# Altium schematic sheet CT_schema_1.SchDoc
size 620 x 511 mm
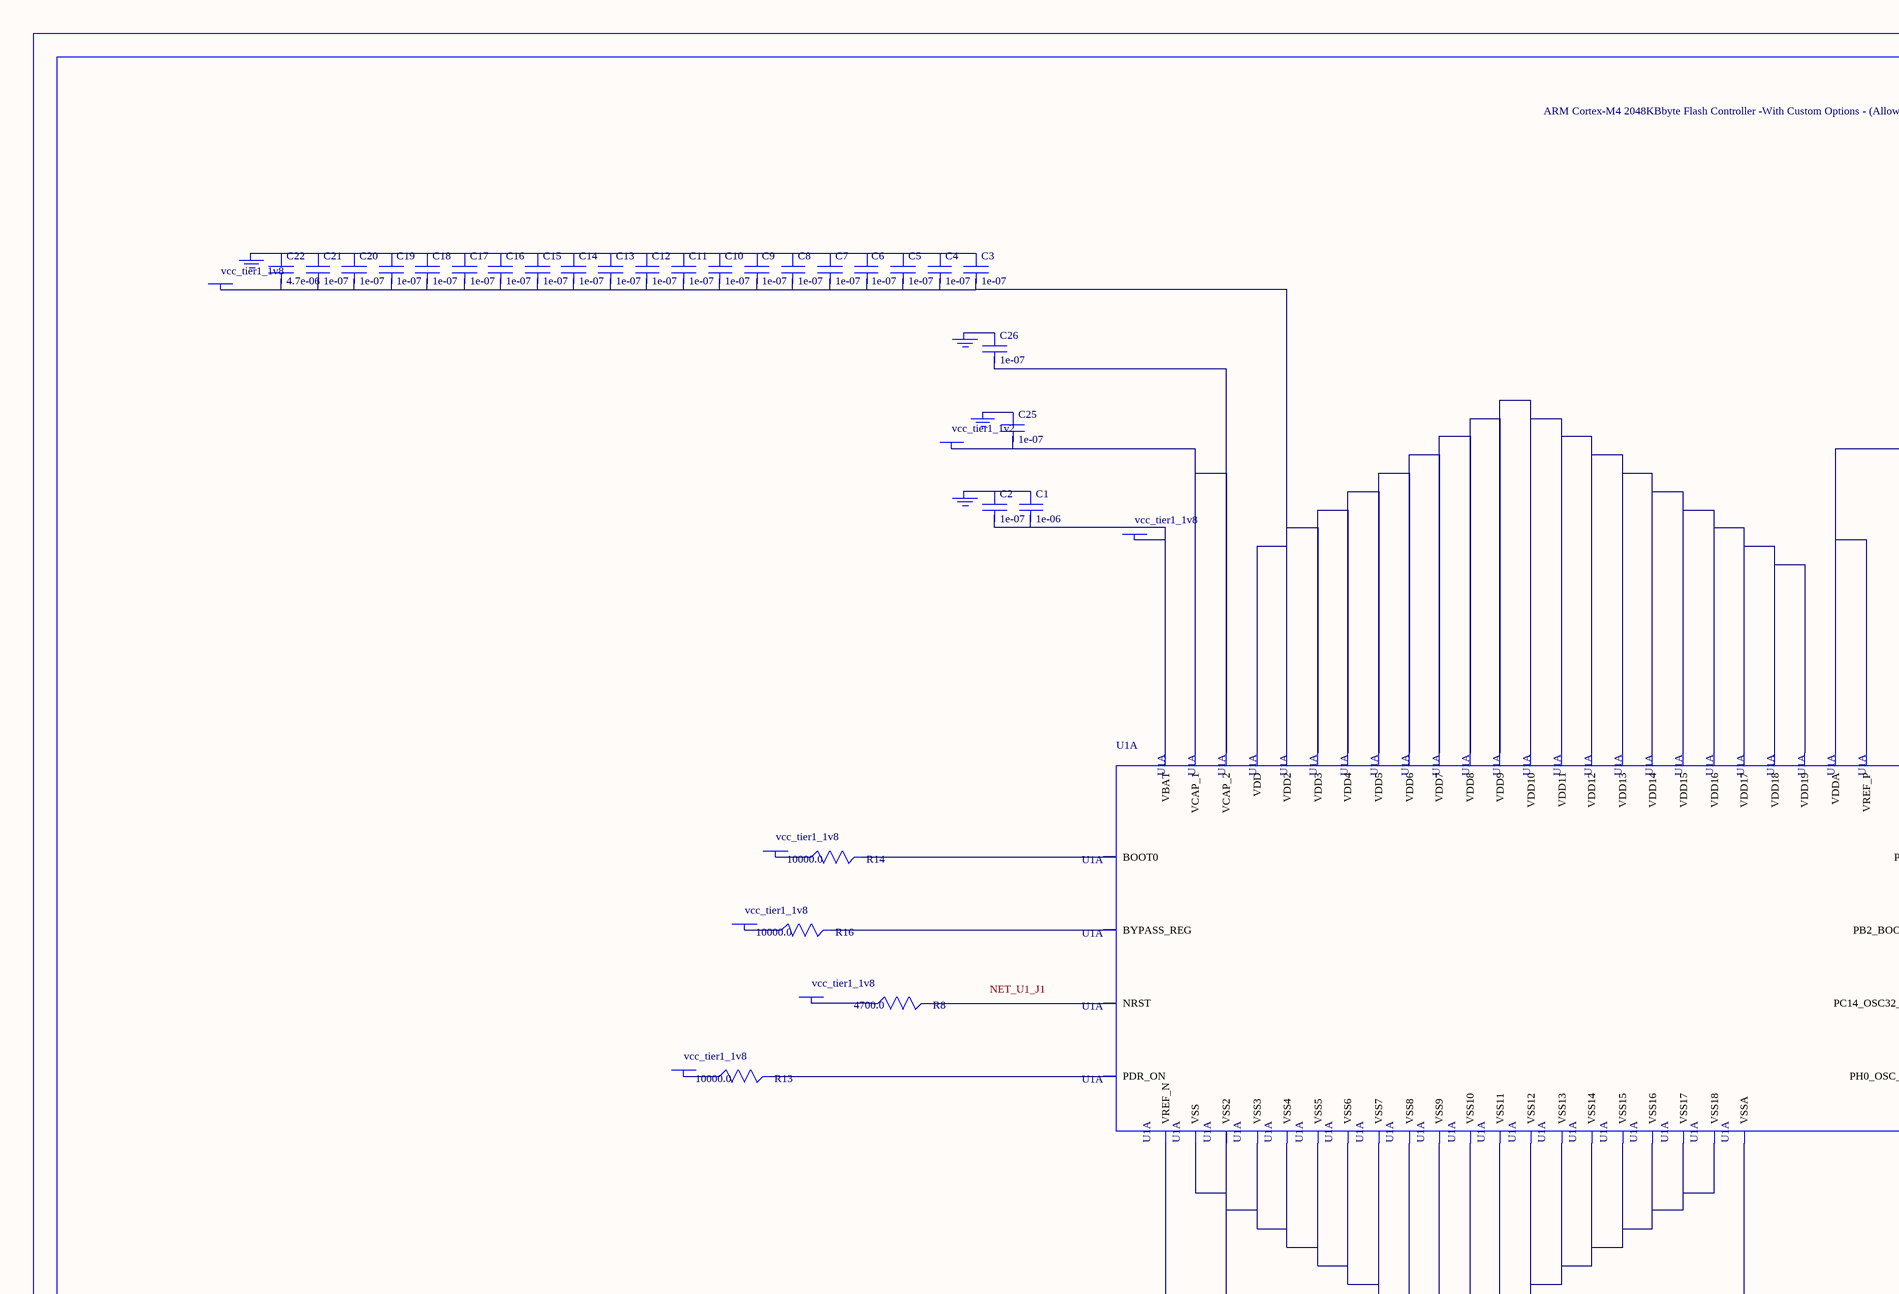
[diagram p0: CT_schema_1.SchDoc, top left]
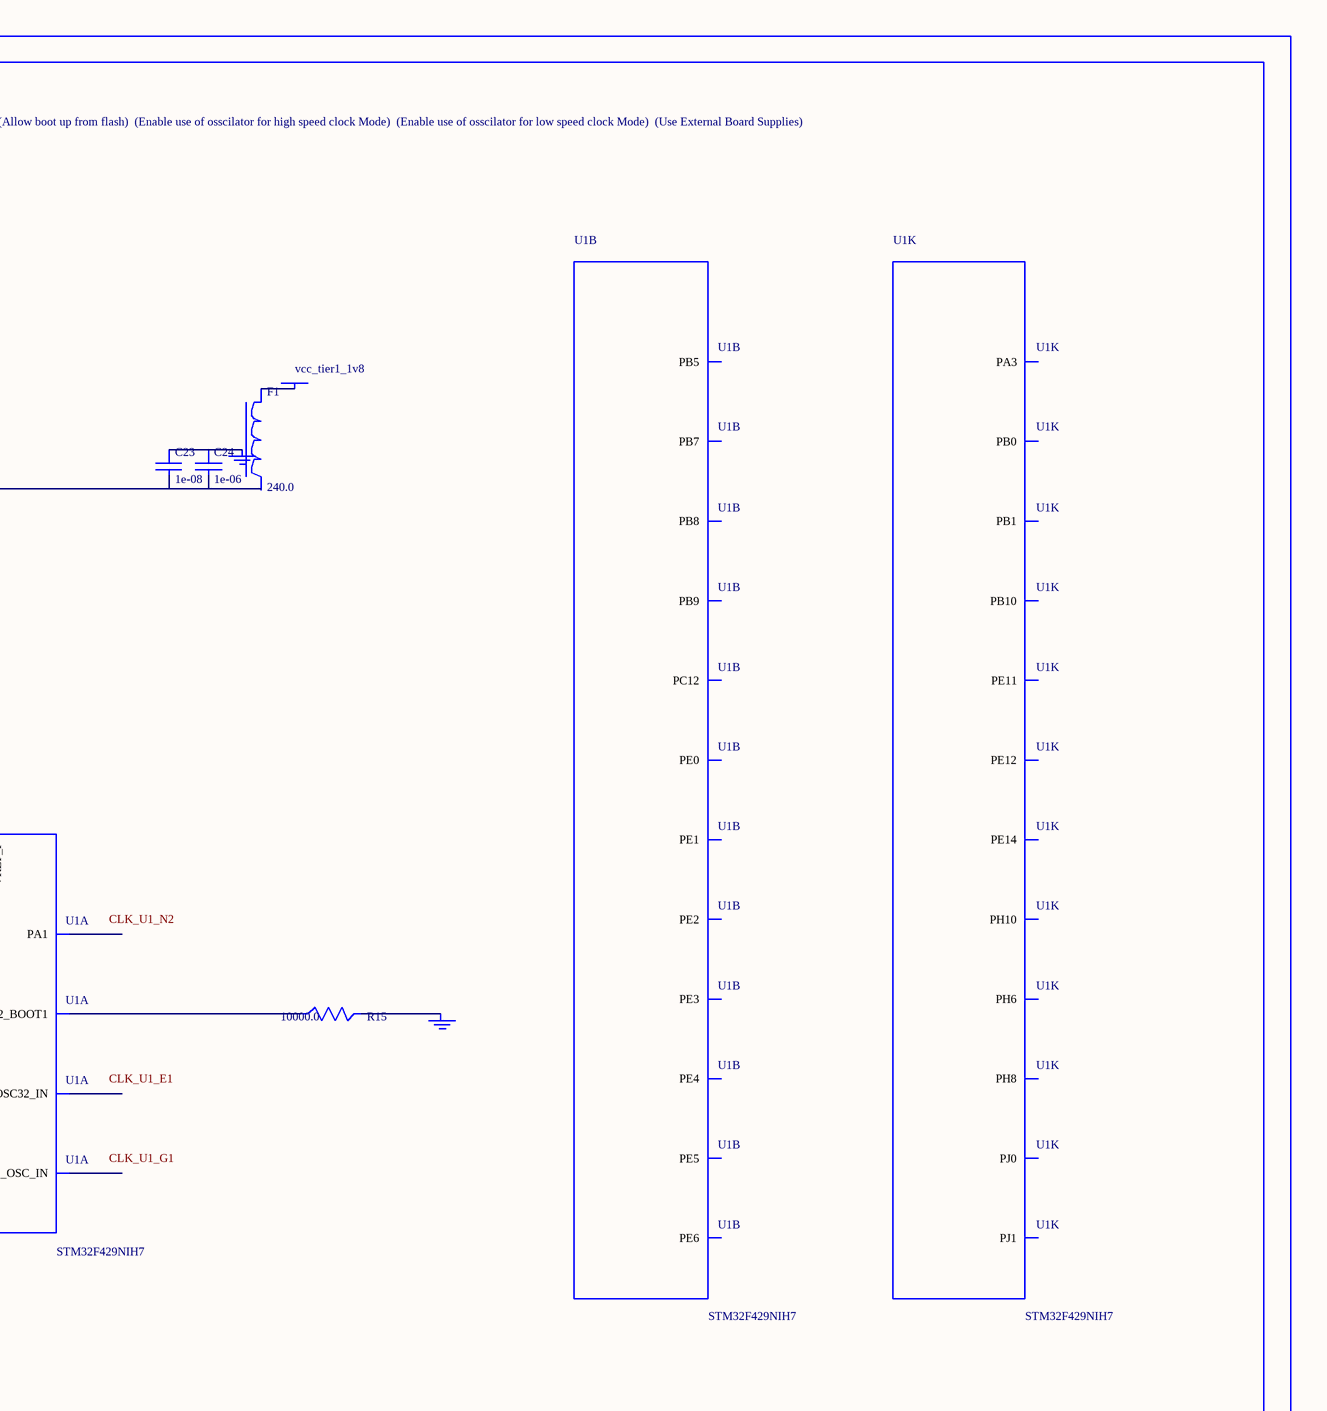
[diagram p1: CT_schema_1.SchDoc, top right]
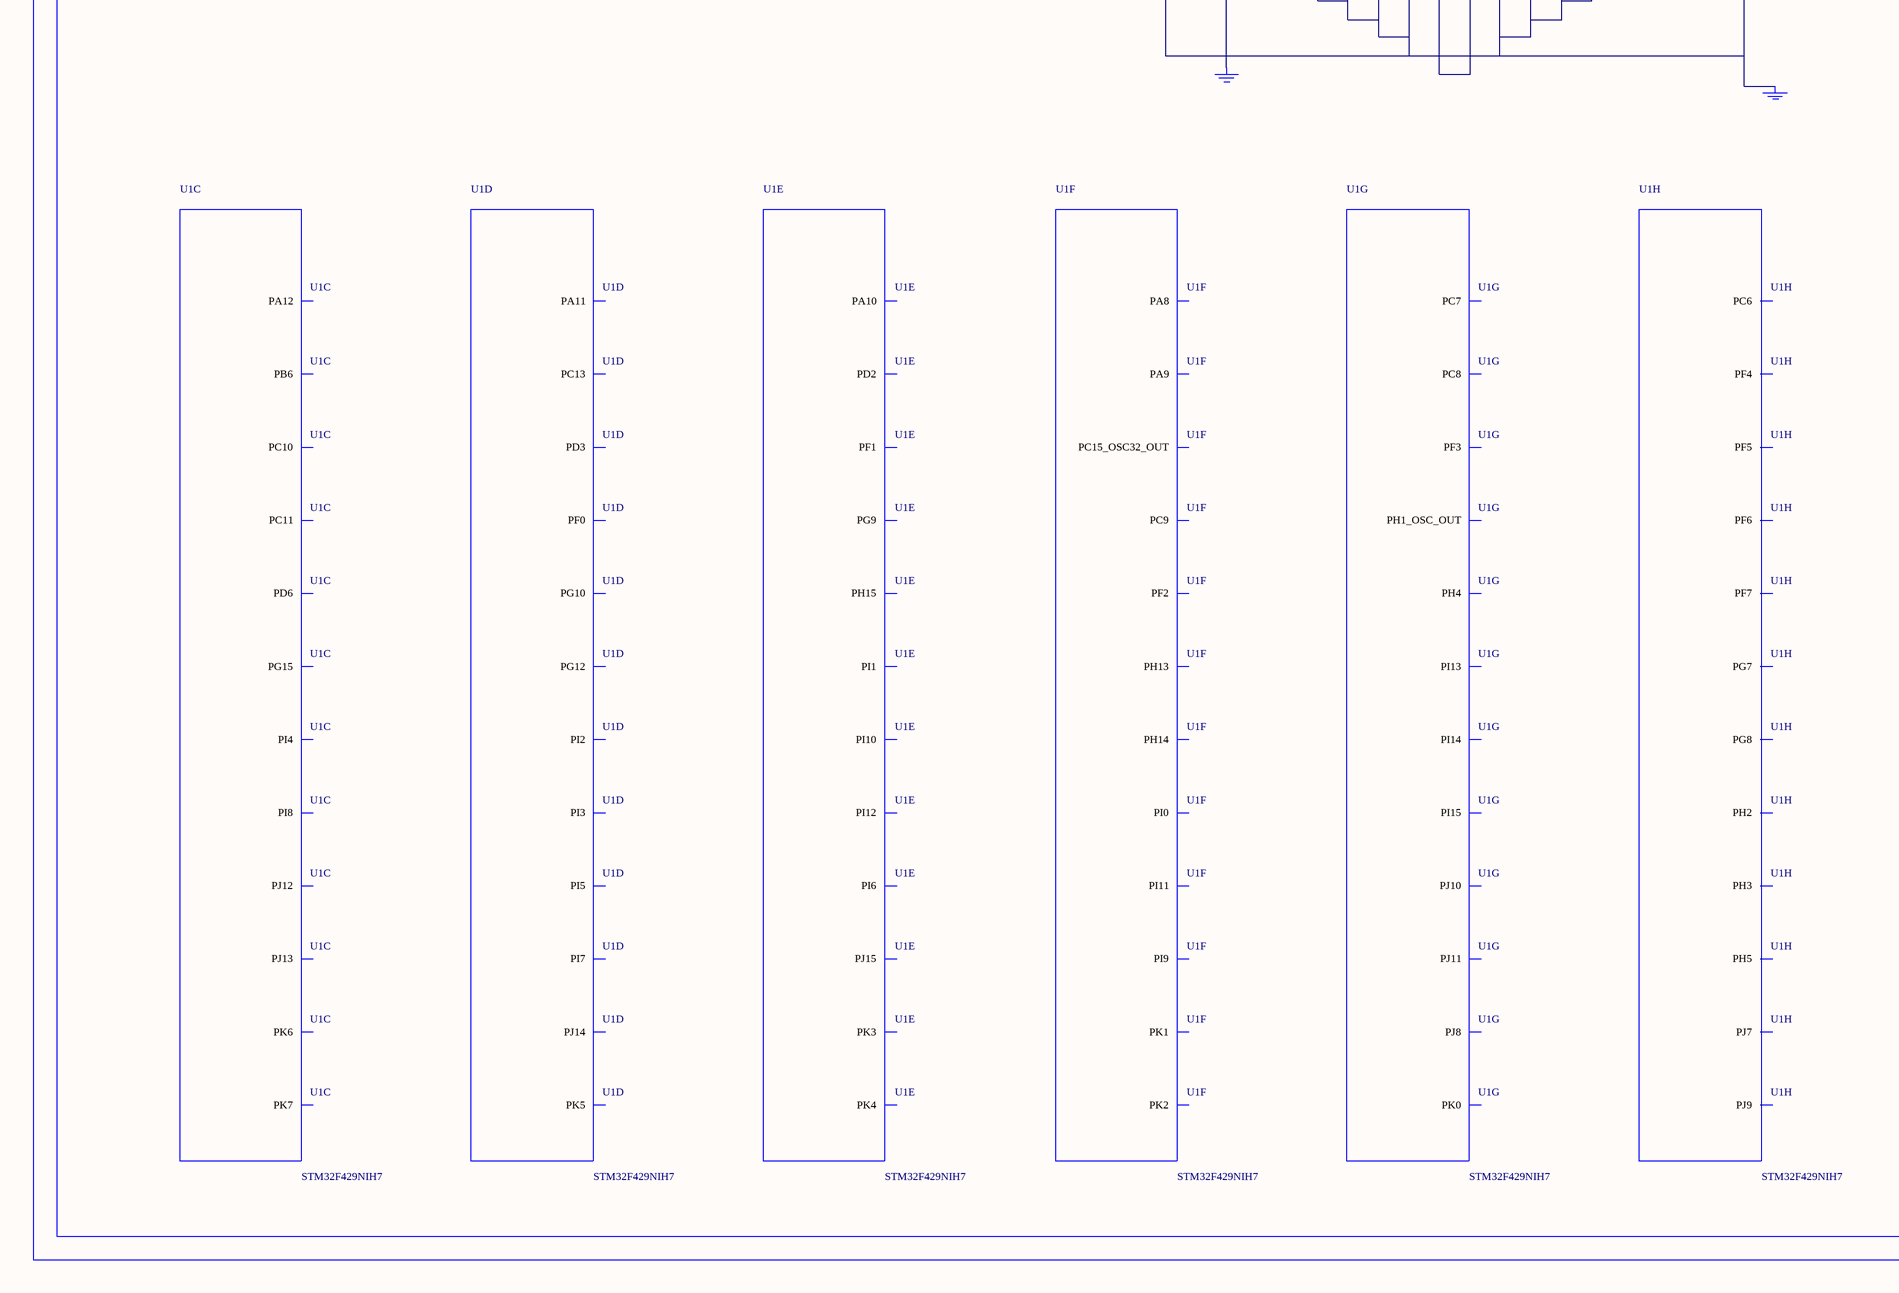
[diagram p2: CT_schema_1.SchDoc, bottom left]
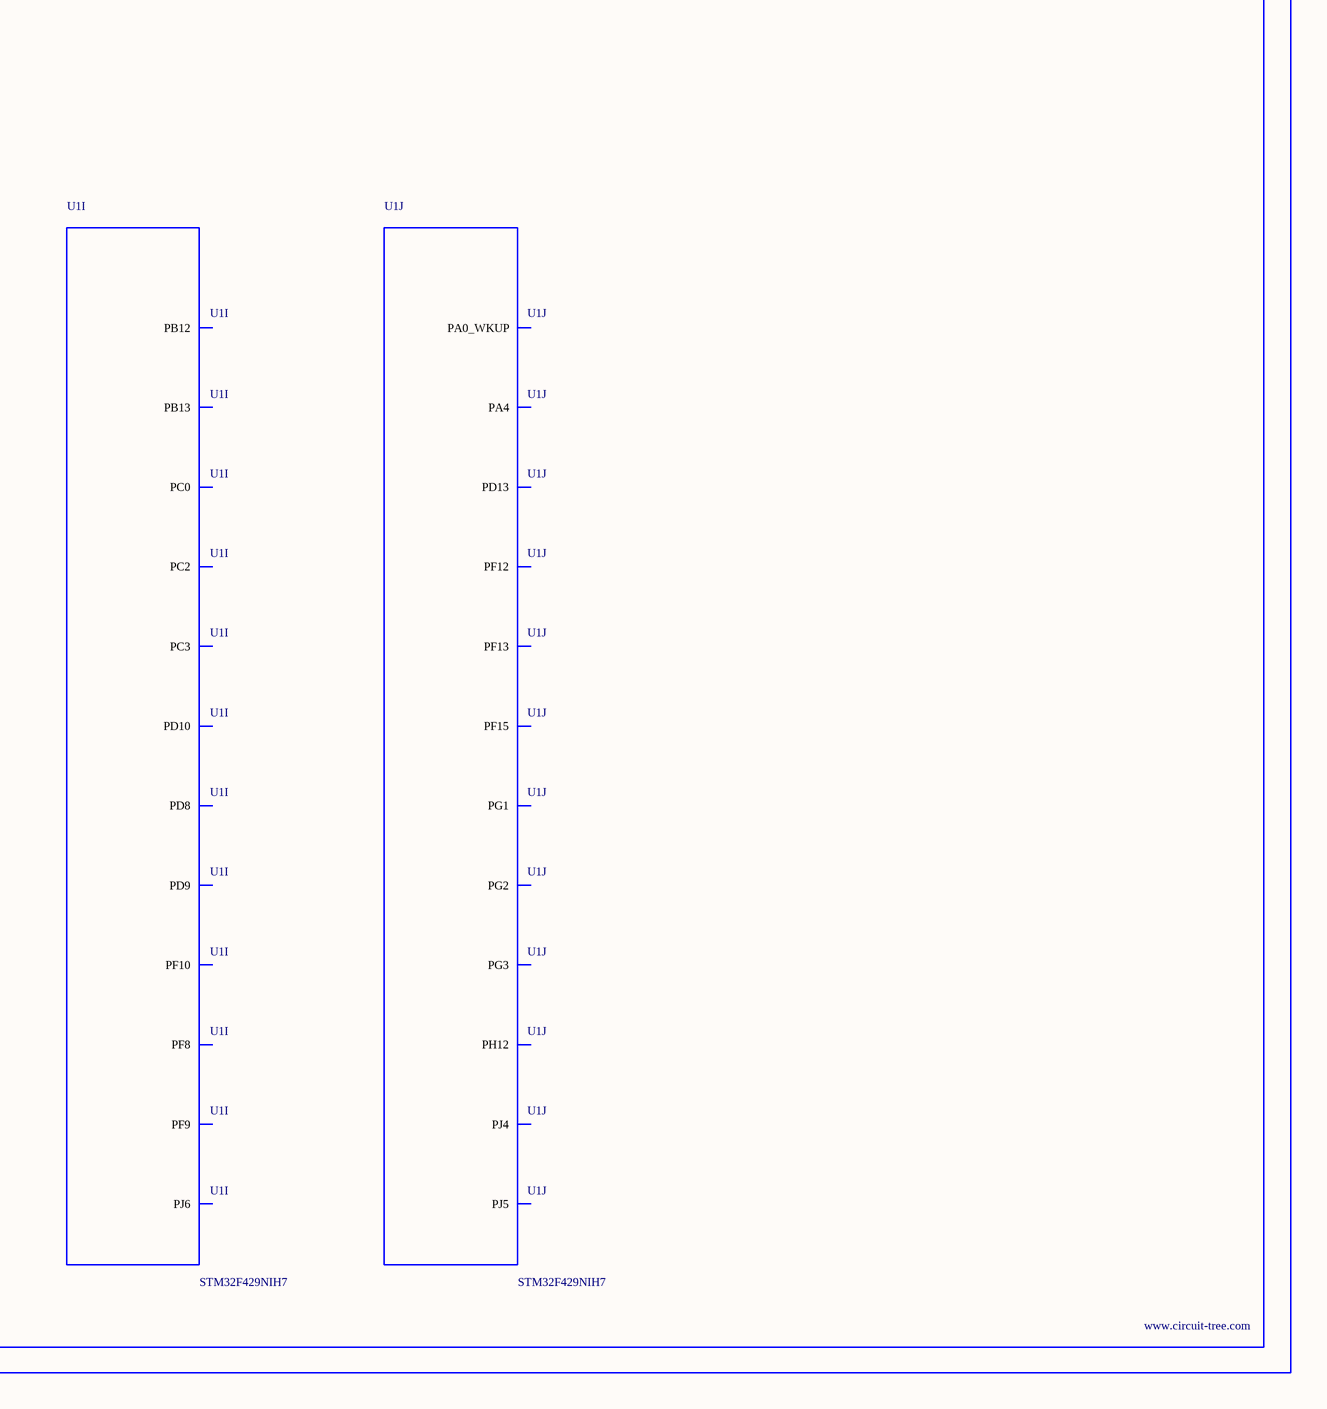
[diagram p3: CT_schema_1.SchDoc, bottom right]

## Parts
BORDER0  (no value)
C1  1e-06  [C0603]
C2  1e-07  [C0603]
C3  1e-07  [C0603]
C4  1e-07  [C0603]
C5  1e-07  [C0603]
C6  1e-07  [C0603]
C7  1e-07  [C0603]
C8  1e-07  [C0603]
C9  1e-07  [C0603]
C10  1e-07  [C0603]
C11  1e-07  [C0603]
C12  1e-07  [C0603]
C13  1e-07  [C0603]
C14  1e-07  [C0603]
C15  1e-07  [C0603]
C16  1e-07  [C0603]
C17  1e-07  [C0603]
C18  1e-07  [C0603]
C19  1e-07  [C0603]
C20  1e-07  [C0603]
C21  1e-07  [C0603]
C22  4.7e-06  [C0603]
C23  1e-08  [C0603]
C24  1e-06  [C0603]
C25  1e-07  [C0402]
C26  1e-07  [C0402]
F1  240.0  [L0603]
GND_INSTANCE_0_0  (no value)
GND_INSTANCE_0_1  (no value)
GND_INSTANCE_0_2  (no value)
GND_INSTANCE_0_3  (no value)
GND_INSTANCE_0_4  (no value)
GND_INSTANCE_0_5  (no value)
GND_INSTANCE_0_6  (no value)
GND_INSTANCE_0_7  (no value)
POWER_INSTANCE_0_0  vcc_tier1_1v8
POWER_INSTANCE_0_1  vcc_tier1_1v8
POWER_INSTANCE_0_2  vcc_tier1_1v8
POWER_INSTANCE_0_3  vcc_tier1_1v8
POWER_INSTANCE_0_4  vcc_tier1_1v8
POWER_INSTANCE_0_5  vcc_tier1_1v8
POWER_INSTANCE_0_6  vcc_tier1_1v2
POWER_INSTANCE_0_7  vcc_tier1_1v8
R8  4700.0  [R0603]
R13  10000.0  [R0603]
R14  10000.0  [R0603]
R15  10000.0  [R0603]
R16  10000.0  [R0603]
U1  STM32F429NIH7  [TFBGA216]  (parts A,B,C,D,E,F,G,H,I,J,K of 16)

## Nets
NetC1_1: C1.1 C2.1 GND_INSTANCE_0_0.0(GND)
NetC1_2: C1.2 C2.2 POWER_INSTANCE_0_0.0(PWR) U1.C1(VBAT)
NetC3_1: C3.1 C4.1 C5.1 C6.1 C7.1 C8.1 C9.1 C10.1 C11.1 C12.1 C13.1 C14.1 C15.1 C16.1 C17.1 C18.1 C19.1 C20.1 C21.1 C22.1 GND_INSTANCE_0_2.0(GND)
NetC3_2: C3.2 C4.2 C5.2 C6.2 C7.2 C8.2 C9.2 C10.2 C11.2 C12.2 C13.2 C14.2 C15.2 C16.2 C17.2 C18.2 C19.2 C20.2 C21.2 C22.2 POWER_INSTANCE_0_2.0(PWR) U1.E7(VDD2) U1.E8(VDD3) U1.E9(VDD4) U1.E10(VDD) U1.F4(VDD6) U1.F5(VDD7) U1.F11(VDD5) U1.G5(VDD9) U1.G11(VDD8) U1.H5(VDD11) U1.H11(VDD10) U1.J5(VDD13) U1.J11(VDD12) U1.K5(VDD15) U1.K11(VDD14) U1.L7(VDD17) U1.L8(VDD18) U1.L9(VDD19) U1.L10(VDD16)
NetC23_1: C23.1 C24.1 GND_INSTANCE_0_1.0(GND)
NetC23_2: C23.2 C24.2 U1.P1(VREF_P) U1.R1(VDDA)
NetC25_1: C25.1 GND_INSTANCE_0_4.0(GND)
NetC25_2: C25.2 C26.2 POWER_INSTANCE_0_6.0(PWR) U1.E11(VCAP_2) U1.L11(VCAP_1)
NetC26_1: C26.1 GND_INSTANCE_0_5.0(GND)
NetF1_1: F1.1 POWER_INSTANCE_0_1.0(PWR)
NetGND_INSTANCE_0_3_0: GND_INSTANCE_0_3.0(GND) R15.2
NetGND_INSTANCE_0_6_0: GND_INSTANCE_0_6.0(GND) GND_INSTANCE_0_7.0(GND) U1.F2(VSS2) U1.F6(VSS3) U1.F7(VSS4) U1.F8(VSS5) U1.F9(VSS6) U1.F10(VSS) U1.G6(VSS8) U1.G10(VSS7) U1.H6(VSS10) U1.H10(VSS9) U1.J6(VSS12) U1.J10(VSS11) U1.K6(VSS14) U1.K7(VSS15) U1.K8(VSS16) U1.K9(VSS17) U1.K10(VSS13) U1.L6(VSS18) U1.M1(VSSA) U1.N1(VREF_N)
NetPOWER_INSTANCE_0_3_0: POWER_INSTANCE_0_3.0(PWR) R13.1
NetPOWER_INSTANCE_0_4_0: POWER_INSTANCE_0_4.0(PWR) R14.1
NetPOWER_INSTANCE_0_5_0: POWER_INSTANCE_0_5.0(PWR) R16.1
NetPOWER_INSTANCE_0_7_0: POWER_INSTANCE_0_7.0(PWR) R8.1
NetR8_2: R8.2 U1.J1(NRST)
NetR13_2: R13.2 U1.E5(PDR_ON)
NetR14_2: R14.2 U1.E6(BOOT0)
NetR15_1: R15.1 U1.M5(PB2_BOOT1)
NetR16_2: R16.2 U1.L5(BYPASS_REG)

Not connected (* = marked no-connect by the designer): F1 2; U1 A1(PE4) A2(PE3) A3(PE2) A5(PE1) A6(PE0) A7(PB8) A8(PB5) A12(PC12) B1(PE5) B2(PE6) B4(PB9) B5(PB7) B6(PB6) B7(PG15) B9(PJ13) B10(PJ12) B11(PD6) B13(PC11) B14(PC10) B15(PA12) C2(PI8) C3(PI4) C4(PK7) C5(PK6) C6(PK5) C7(PG12) C8(PG10) C9(PJ14) C11(PD3) C13(PI3) C14(PI2) C15(PA11) D1(PC13) D2(PF0) D3(PI5) D4(PI7) D5(PI10) D6(PI6) D7(PK4) D8(PK3) D9(PG9) D10(PJ15) D12(PD2) D13(PH15) D14(PI1) D15(PA10) E1(PC14_OSC32_IN) E2(PF1) E3(PI12) E4(PI9) E12(PH13) E13(PH14) E14(PI0) E15(PA9) F1(PC15_OSC32_OUT) F3(PI11) F12(PK1) F13(PK2) F14(PC9) F15(PA8) G1(PH0_OSC_IN) G2(PF2) G3(PI13) G4(PI15) G12(PJ11) G13(PK0) G14(PC8) G15(PC7) H1(PH1_OSC_OUT) H2(PF3) H3(PI14) H4(PH4) H12(PJ8) H13(PJ10) H14(PG8) H15(PC6) J2(PF4) J3(PH5) J4(PH3) J12(PJ7) J13(PJ9) J14(PG7) K1(PF7) K2(PF6) K3(PF5) K4(PH2) K12(PJ6) K14(PB13) K15(PD10) L1(PF10) L2(PF9) L3(PF8) L4(PC3) L13(PB12) L14(PD9) L15(PD8) M2(PC0) M4(PC2) M6(PF12) M7(PG1) M8(PF15) M9(PJ4) M11(PD13) M12(PG3) M13(PG2) M14(PJ5) M15(PH12) N2(PA1) N3(PA0_WKUP) N4(PA4) N6(PF13) P10(PE11) P11(PE14) P12(PB10) P13(PH6) P14(PH8) P15(PH10) R2(PA3) R4(PB1) R5(PB0) R6(PJ0) R7(PJ1) R10(PE12)

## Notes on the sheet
- Labels drawn without touching a wire or pin: CLK_U1_E1, CLK_U1_G1, CLK_U1_N2, NET_U1_J1

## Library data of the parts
BORDER0 = BORDER_PAGE0
C1 C24 = C0603C105K3RACTU
C2-C21 = 06035C104K4Z2A
C22 = GRM188R6YA475KE15D
C23 = 06035C103K4Z2A
C25 C26 = C0402C104K3RACTU
F1 = Z0603C241ASMST
GND_INSTANCE_0_0-GND_INSTANCE_0_7 = GND
POWER_INSTANCE_0_0-POWER_INSTANCE_0_7 = PWR
R8 = RC0603JR-074K7L
R13-R16 = RC0603JR-0710KL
